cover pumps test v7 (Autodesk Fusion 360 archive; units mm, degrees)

design "cover pumps test" references "magnetventil halter cocktail", "frame", "new vertical motor mount"
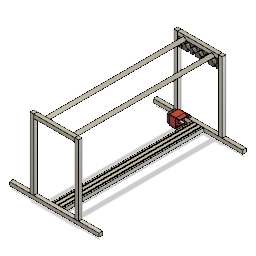
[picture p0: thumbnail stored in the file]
component_insert "Komponente einfügen1"
component_insert "Komponente einfügen2"
position "Position1"
component_insert "Komponente einfügen3"

design "new vertical motor mount"
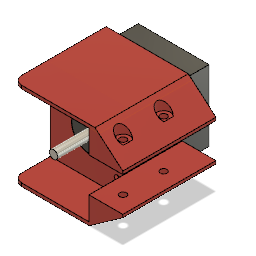
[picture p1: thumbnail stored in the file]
parameter "acryl" = 5
parameter "d6" = 13 (= "20 mm - 7 mm")
sketch "Sketch1" plane through (0, 0, 0) normal (0, 0, 1) x axis (1, 0, 0)
  line L1 (-21, 18) -> (-21, 4)
  line L2 (18, 21) -> (-18, 21)
  line L3 (21, 4) -> (21, 18)
  line L4 (-21, 21) -> (21, -21)
  line L5 (21, 21) -> (-21, -21)
  line L6 (-41, -39) -> (-41, -31)
  line L7 (41, -39) -> (-41, -39)
  line L8 (41, -31) -> (41, -39)
  line L9 (-41, -14) -> (-39, -14)
  line L10 (-41, -31) -> (-41, -17.9089)
  line L11 (41, -14) -> (39, -14)
  line L12 (41, -31) -> (41, -17.9089)
  line L13 (0, 22.5) -> (0, 1.75)
  circle C1 centre (15.5, 15.5) radius 1.7
  circle C2 centre (-15.5, 15.5) radius 1.7
  circle C3 centre (-15.5, -15.5) radius 1.7
  circle C4 centre (15.5, -15.5) radius 1.7
  circle C5 centre (-31, -29) radius 2.05
  circle C6 centre (31, -29) radius 2.05
  arc A1 centre (-39, 4) radius 18 clockwise from (-21, 4) to (-37.3636, -13.9255)
  arc A2 centre (39, 4) radius 18 clockwise from (37.3636, -13.9255) to (21, 4)
  circle C7 centre (0, 0) radius 11.5
  circle C8 centre (0, -29) radius 2.05
  arc A3 centre (-18, 18) radius 3 clockwise from (-21, 18) to (-18, 21)
  arc A4 centre (18, 18) radius 3 clockwise from (18, 21) to (21, 18)
  arc A5 centre (-37, -17.9089) radius 4 clockwise from (-41, -17.9089) to (-37.3636, -13.9255)
  arc A6 centre (37, -17.9089) radius 4 clockwise from (37.3636, -13.9255) to (41, -17.9089)
  point P6 (0, 0)
  point P1 (0, 0)
  point P7 (15.5, 15.5)
  point P27 (0, 0)
  point P28 (0, -29)
  point P4 (-21, 21)
  point P5 (21, 21)
  point P2 (21, -21)
  point P17 (-31, -29)
  parallel L1 L3
  coincident L4 P6
  coincident L5 P6
  coincident P1 P6
  coincident L5 P7
  vertical L6
  horizontal L7
  vertical L8
  horizontal L9
  vertical L10
  horizontal L11
  vertical L12
  symmetric C5 L13 C6
  tangent L9 A1
  tangent L1 A1
  tangent L11 A2
  tangent L3 A2
  equal A1 A2
  coincident P1 P27
  vertical P27 P28
  coincident P4 L1
  coincident P4 L2
  tangent L1 A3
  tangent L2 A3
  coincident P5 L2
  coincident P5 L3
  tangent L2 A4
  tangent L3 A4
  tangent L10 A5
  tangent A1 A5
  tangent L12 A6
  tangent A2 A6
  dimension "d1" distance P2 P5 = 42
  dimension "d2" distance P1 P7 = 15.5 (= "( 31 / 2 ) * 1 mm")
  dimension "d3" diameter C1 = 3.4
  dimension "d8" distance L3 L8 = 20
  dimension "d9" distance L1 L6 = 20
  dimension "d11" distance L7 L9 = 25
  dimension "d12" diameter C5 = 4.1
  dimension "d13" distance L9 P17 = 15
  dimension "d14" distance L6 P17 = 10
  dimension "d15" radius A1 = 18
  dimension "d20" diameter C7 = 23
  dimension "d23" diameter C8 = 4.1
  dimension "d30" radius A3 = 3
  dimension "d31" radius A4 = 3
  dimension "d32" radius A5 = 4
  dimension "d33" radius A6 = 4
  dimension "d5" C-Pattern1-Angle = 360
work_plane "WorkPlane1" AlongDistance 0
sketch "Path Offsets" plane through (0, 0, 1) normal (0, 0, 1) x axis (1, 0, 0)
  line L1 (-41, -39) -> (-41, -17.9089)
  line L2 (41, -39) -> (-41, -39)
  line L3 (41, -17.9089) -> (41, -39)
  line L4 (21, 18) -> (21, 4)
  line L5 (-18, 21) -> (18, 21)
  line L6 (-21, 4) -> (-21, 18)
  line L7 (-41, -39) -> (-41, -14)
  line L8 (41, -39) -> (-41, -39)
  line L9 (41, -14) -> (41, -39)
  line L10 (39, -14) -> (41, -14)
  line L11 (21, 21) -> (21, 4)
  line L12 (-21, 21) -> (21, 21)
  line L13 (-21, 4) -> (-21, 21)
  line L14 (-41, -14) -> (-39, -14)
  circle C1 centre (-15.5, -15.5) radius 1.7
  circle C2 centre (0, 0) radius 11.5
  circle C3 centre (15.5, -15.5) radius 1.7
  circle C4 centre (-31, -29) radius 2.05
  circle C5 centre (-15.5, 15.5) radius 1.7
  circle C6 centre (15.5, 15.5) radius 1.7
  circle C7 centre (31, -29) radius 2.05
  circle C8 centre (0, -29) radius 2.05
  arc A1 centre (39, 4) radius 18 clockwise from (37.3636, -13.9255) to (21, 4)
  arc A2 centre (-39, 4) radius 18 clockwise from (-21, 4) to (-37.3636, -13.9255)
  arc A3 centre (39, 4) radius 18 clockwise from (39, -14) to (21, 4)
  arc A4 centre (-39, 4) radius 18 clockwise from (-21, 4) to (-39, -14)
  arc A5 centre (18, 18) radius 3 clockwise from (18, 21) to (21, 18)
  arc A6 centre (-18, 18) radius 3 clockwise from (-21, 18) to (-18, 21)
  arc A7 centre (-37, -17.9089) radius 4 clockwise from (-41, -17.9089) to (-37.3636, -13.9255)
  arc A8 centre (37, -17.9089) radius 4 clockwise from (37.3636, -13.9255) to (41, -17.9089)
  parallel L1 L7
  parallel L2 L8
  parallel L3 L9
  concentric A1 A3
  parallel L4 L11
  parallel L5 L12
  parallel L6 L13
  concentric A2 A4
  tangent L13 A4
  tangent A4 L14
  tangent A3 L11
  tangent L10 A3
sketch "Perimeter" plane through (0, -11.5, 1) normal (0, 0, 1) x axis (1, 0, 0)
  line L1 (39, -2.5) -> (41, -2.5)
  line L2 (41, -2.5) -> (41, -27.5)
  line L3 (41, -27.5) -> (-41, -27.5)
  line L4 (-41, -27.5) -> (-41, -2.5)
  line L5 (-41, -2.5) -> (-39, -2.5)
  line L6 (-21, 15.5) -> (-21, 32.5)
  line L7 (-21, 32.5) -> (21, 32.5)
  line L8 (21, 32.5) -> (21, 15.5)
  arc A1 centre (-39, 15.5) radius 18 clockwise from (-21, 15.5) to (-39, -2.5)
  arc A2 centre (39, 15.5) radius 18 clockwise from (39, -2.5) to (21, 15.5)
sketch "Cutouts" plane through (0, -11.5, 1) normal (0, 0, 1) x axis (1, 0, 0)
  circle C1 centre (-15.5, -4) radius 1.625
  circle C2 centre (0, 11.5) radius 11.425
  circle C3 centre (15.5, -4) radius 1.625
  circle C4 centre (-31, -17.5) radius 1.975
  circle C5 centre (-15.5, 27) radius 1.625
  circle C6 centre (15.5, 27) radius 1.625
  circle C7 centre (31, -17.5) radius 1.975
  circle C8 centre (0, -17.5) radius 1.975
remove_instance "RemoveInstance1"
sketch "Sketch1" plane through (0, 0, 0) normal (0, 0, 1) x axis (1, 0, 0)
  line L1 (0, 21) -> (0, 0)
  line L2 (19, 0) -> (0, 0)
  line L3 (21, 21) -> (-21, 21)
  line L4 (21, -21) -> (21, 21)
  line L5 (-21, -21) -> (21, -21)
  line L6 (-21, 21) -> (-21, -21)
  circle C1 centre (0, 0) radius 11.5
  circle C2 centre (-15.5, 15.5) radius 1.7
  circle C3 centre (15.5, 15.5) radius 1.7
  circle C4 centre (15.5, -15.5) radius 1.7
  circle C5 centre (-15.5, -15.5) radius 1.7
  circle C6 centre (0, 0) radius 2.5
  point P1 (0, 0)
  point P2 (0, 0)
  point P4 (0, 0)
  point P5 (0, 0)
  point P15 (0, 0)
  point P11 (-21, 21)
  point P12 (21, 21)
  point P14 (-21, -21)
  coincident P1 P2
  vertical L1
  coincident P1 P4
  coincident P4 P5
  perpendicular L1 L2
  horizontal L3
  vertical L4
  horizontal L5
  vertical L6
  coincident P1 P15
  dimension "d16" diameter C1 = 23
  dimension "d18" distance P11 P12 = 42
  dimension "d19" distance P11 P14 = 42
  dimension "d21" distance L2 L3 = 21 (= "d19 / 2")
  dimension "d22" distance L1 L6 = 21 (= "d18 / 2")
  dimension "d29" diameter C6 = 5
extrude "Extrude1" new body sketch "Sketch1" profile of C1 C2 C3 C4 C5 L3 L4 L5 L6 against normal blind 47 bodies "motor"
extrude "Extrude2" add sketch "Sketch1" profile of C1 along normal blind 1.85
extrude "Extrude3" new body sketch "Sketch1" profile of C6 along normal blind 24.15 (= "71.15 mm - 47 mm") bodies "motorshaft"
combine "Combine1"
sketch "Sketch2" plane through (0, 0, 0) normal (0, 0, 1) x axis (1, 0, 0)
  line L1 (21, -21) -> (-21, -21)
  line L2 (21, 21) -> (21, -21)
  line L3 (-21, 21) -> (21, 21)
  line L4 (-21, -21) -> (-21, 21)
  line L5 (41, 10) -> (21, 10)
  line L6 (41, -10) -> (41, 10)
  line L7 (21, -10) -> (41, -10)
  line L8 (21, 10) -> (21, -10)
  line L9 (21, 0) -> (41, 0)
  line L10 (-24, 24) -> (24, 24)
  line L11 (-24, -24) -> (-24, 24)
  line L12 (24, -24) -> (-24, -24)
  line L13 (24, 24) -> (24, -24)
  line L14 (26.8952, 24) -> (24, 24)
  line L15 (41, 12) -> (26.8952, 24)
  line L16 (41, -12) -> (41, 12)
  line L17 (24, -24) -> (41, -12)
  circle C1 centre (0, 0) radius 11.5
  circle C2 centre (-15.5, 15.5) radius 1.7
  circle C3 centre (15.5, 15.5) radius 1.7
  circle C4 centre (-15.5, -15.5) radius 1.7
  circle C5 centre (15.5, -15.5) radius 1.7
  point P11 (21, 10)
  point P15 (41, 0)
  point P16 (21, 0)
  point P12 (41, 10)
  point P14 (21, -10)
  point P22 (41, 12)
  point P23 (41, -12)
  horizontal L5
  vertical L6
  horizontal L7
  vertical L8
  coincident L2 P11
  midpoint L6 P15
  midpoint L8 P16
  perpendicular L13 L14
  perpendicular L14 L16
  collinear L6 L16
  dimension "d36" distance P11 P12 = 20
  dimension "d37" distance P11 P14 = 20
  dimension "d38" distance L1 L3 = 42
  dimension "d39" distance L3 L9 = 21 (= "42.00 mm / 2")
  dimension "d40" = 3
  dimension "d41" distance P22 P23 = 24
  dimension "d42" distance L9 P22 = 12 (= "d41 / 2")
extrude "Extrude4" new body sketch "Sketch2" profile of L2 L5 L6 L7 L8 L16 against normal blind 70 and along normal blind 50 bodies "alurail"
extrude "Extrude5" new body sketch "Sketch2" profile of C1 C2 C3 C4 C5 L1 L2 L3 L4 L5 L7 L8 L12 L11 L10 L14 L15 L16 L17 along normal blind 2 bodies "holder"
copy_paste_bodies "CutPasteBodies1"
copy_paste_bodies "CutPasteBodies1"
extrude "Extrude6" add sketch "Sketch2" profile of L1 L2 L3 L4 L5 L7 L12 L11 L10 L14 L15 L16 L17 against normal blind 47
sketch "Sketch3" plane through (0, 24, 0) normal (0, 1, 0) x axis (-1, 0, 0)
  line L1 (24, 2) -> (24, -47)
  line L2 (-26.8952, 2) -> (24, 2)
  line L3 (-26.8952, -47) -> (-26.8952, 2)
  line L4 (24, -47) -> (-26.8952, -47)
sketch "Sketch1" plane through (0, -10, 0) normal (0, 1, 0) x axis (-1, 0, 0)
  line L1 (-21, 2) -> (-21, 0)
  line L2 (-41, 2) -> (-21, 2)
  line L3 (-41, -47) -> (-41, 2)
  line L4 (-21, -47) -> (-41, -47)
  line L5 (-21, 0) -> (-21, -47)
  line L6 (-31, 2) -> (-31, -47)
  line L7 (-21, -22.5) -> (-41, -22.5)
  circle C1 centre (-31, -10) radius 2
  circle C2 centre (-31, -10) radius 4
  circle C3 centre (-31, -35) radius 4
  circle C4 centre (-31, -35) radius 2
  point P7 (-31, -47)
  point P8 (-31, 2)
  point P9 (-31, -10)
  point P11 (-41, -22.5)
  point P12 (-21, -22.5)
  midpoint L4 P7
  midpoint L2 P8
  coincident L6 P9
  concentric C1 C2
  midpoint L3 P11
  coincident L5 P12
  perpendicular L5 L7
  symmetric C1 L7 C4
  symmetric C2 L7 C3
  dimension "d51" diameter C1 = 4
  dimension "d52" diameter C2 = 8
  dimension "d53" distance L2 P9 = 12
position "Position1"
extrude "Extrude7" cut sketch "Sketch1" profile of C1 C4 against normal blind 56
extrude "Extrude8" cut sketch "Sketch1" profile of C1 C2 C3 C4 against normal blind 10
position "Position2"
extrude "Extrude9" cut sketch "Sketch1" profile of C1 C2 C3 C4 along normal blind 25
sketch "Sketch2" plane through (0, 0, 2) normal (0, 0, 1) x axis (1, 0, 0)
  line L1 (21, 22) -> (41, 22)
  line L2 (21, 42) -> (21, 22)
  line L3 (41, 42) -> (21, 42)
  line L4 (41, 44) -> (41, 42)
  line L5 (26.8952, 56) -> (41, 44)
  line L6 (-24, 56) -> (26.8952, 56)
  line L7 (-24, 8) -> (-24, 56)
  line L8 (24, 8) -> (-24, 8)
  line L9 (41, 20) -> (24, 8)
  line L10 (41, 22) -> (41, 20)
  circle C1 centre (0, 32) radius 11.5
  circle C2 centre (-15.5, 47.5) radius 1.7
  circle C3 centre (15.5, 47.5) radius 1.7
  circle C4 centre (-15.5, 16.5) radius 1.7
  circle C5 centre (15.5, 16.5) radius 1.7
sketch "Sketch1" plane through (0, -32, 2) normal (0, 0, 1) x axis (1, 0, 0)
  line L1 (26.8952, 8) -> (-24, 8)
  line L2 (21, 22) -> (41, 22)
  line L3 (21, 42) -> (21, 22)
  line L4 (41, 42) -> (21, 42)
  line L5 (41, 44) -> (41, 42)
  line L6 (-24, 56) -> (26.8952, 56)
  line L7 (-24, 8) -> (-24, 56)
  line L8 (28.5, 46) -> (28.5, 42)
  line L9 (33.5, 46) -> (28.5, 46)
  line L10 (33.5, 42) -> (33.5, 46)
  line L11 (21, 42) -> (41, 42)
  line L12 (41, 22) -> (21, 22)
  line L13 (31, 42) -> (31, 22)
  line L14 (21, 32) -> (31, 32)
  line L15 (28.5, 18) -> (28.5, 22)
  line L16 (33.5, 22) -> (33.5, 18)
  line L17 (33.5, 18) -> (28.5, 18)
  line L18 (41, 42) -> (21, 42)
  line L19 (41, 46) -> (41, 42)
  line L20 (21, 46) -> (41, 46)
  line L21 (21, 42) -> (21, 46)
  line L22 (41, 46) -> (26.8952, 56)
  line L23 (21, 22) -> (21, 18)
  line L24 (21, 18) -> (41, 18)
  line L25 (41, 18) -> (41, 22)
  line L26 (41, 18) -> (26.8952, 8)
  point P10 (28.5, 42)
  point P13 (33.5, 42)
  point P18 (31, 22)
  point P19 (31, 42)
  point P20 (31, 32)
  point P21 (21, 32)
  point P22 (28.5, 22)
  point P11 (28.5, 46)
  point P23 (28.5, 18)
  point P12 (33.5, 46)
  point P24 (33.5, 18)
  point P25 (33.5, 22)
  point P3 (26.8952, 56)
  point P33 (26.8952, 8)
  point P7 (21, 42)
  point P30 (21, 22)
  point P26 (41, 42)
  point P32 (41, 22)
  point P27 (41, 46)
  point P31 (41, 18)
  point P28 (21, 46)
  point P29 (21, 18)
  coincident L4 P10
  perpendicular L4 L8
  perpendicular L8 L9
  coincident L4 P13
  perpendicular L4 L10
  midpoint L12 P18
  midpoint L4 P19
  perpendicular L4 L13
  midpoint L13 P20
  midpoint L3 P21
  perpendicular L3 L14
  symmetric P10 L14 P22
  symmetric P11 L14 P23
  symmetric P12 L14 P24
  symmetric P13 L14 P25
  horizontal L18
  vertical L19
  horizontal L20
  vertical L21
  collinear L9 L20
  symmetric P3 L14 P33
  symmetric P7 L14 P30
  symmetric L14 P26 P32
  symmetric L14 P27 P31
  symmetric L14 P28 P29
  dimension "d60" distance P11 P12 = 5 (= "acryl")
  dimension "d62" distance L6 L11 = 14
  dimension "d63" distance L11 L12 = 20
  dimension "d64" distance L3 L13 = 10
  dimension "d65" distance L8 L13 = 2.5 (= "d60 / 2")
extrude "Extrude1" new body sketch "Sketch1" profile of L1 L2 L3 L4 L6 L7 L8 L9 L10 L11 L12 L15 L16 L17 L18 L20 L21 L22 L23 L24 L26 along normal blind 5 (= "acryl")
extrude "Extrude2" cut sketch "Sketch1" profile of C1 C2 C3 C4 C5 C6 along normal blind 14
extrude "Extrude3" cut sketch "Sketch1" profile of C6 along normal blind 9
copy_paste_bodies "CopyPasteBodies1"
move "Move1"
move "Move2"
sketch "Sketch2" plane through (0, 14, 0) normal (0, -1, 0) x axis (1, 0, 0)
  line L1 (28.5, 2) -> (21, 2)
  line L2 (28.5, 7) -> (28.5, 2)
  line L3 (21, 7) -> (28.5, 7)
  line L4 (21, 2) -> (21, 7)
  line L5 (41, 15) -> (21, 15)
  line L6 (41, -62) -> (41, 15)
  line L7 (21, -62) -> (41, -62)
  line L8 (21, 15) -> (21, -62)
  line L9 (-21, 0) -> (21, 0)
  line L10 (-21, -47) -> (21, -47)
  line L11 (21, 5) -> (28.5, 5)
  line L12 (28.5, 5) -> (28.5, 0)
  line L13 (28.5, 0) -> (21, 0)
  line L14 (31, -62) -> (31, 15)
  line L15 (33.5, 5) -> (33.5, 0)
  line L16 (41, 5) -> (33.5, 5)
  line L17 (33.5, 0) -> (41, 0)
  line L18 (21, -23.5) -> (41, -23.5)
  line L19 (28.5, -47) -> (21, -47)
  line L20 (28.5, -52) -> (28.5, -47)
  line L21 (21, -52) -> (28.5, -52)
  line L22 (33.5, -47) -> (41, -47)
  line L23 (33.5, -52) -> (33.5, -47)
  line L24 (41, -52) -> (33.5, -52)
  circle C1 centre (31, -9.9855) radius 2
  circle C2 centre (31, -37.0145) radius 2
  point P18 (31, 15)
  point P19 (31, -62)
  point P14 (28.5, 5)
  point P21 (33.5, 5)
  point P15 (21, 5)
  point P22 (41, 5)
  point P16 (21, 0)
  point P23 (41, 0)
  point P17 (28.5, 0)
  point P20 (33.5, 0)
  point P24 (41, -23.5)
  point P25 (21, -23.5)
  point P28 (28.5, -52)
  point P29 (21, -52)
  point P26 (21, -47)
  point P27 (28.5, -47)
  point P31 (33.5, -47)
  point P32 (33.5, -52)
  point P33 (41, -52)
  point P30 (41, -47)
  point P34 (31, -9.9855)
  point P6 (21, 15)
  point P7 (41, 15)
  horizontal L5
  vertical L6
  horizontal L7
  vertical L8
  midpoint L5 P18
  midpoint L7 P19
  symmetric P14 L14 P21
  symmetric P15 L14 P22
  symmetric P16 L14 P23
  symmetric P17 L14 P20
  midpoint L6 P24
  midpoint L8 P25
  collinear L9 L13
  symmetric P14 L18 P28
  symmetric P15 L18 P29
  symmetric P16 L18 P26
  symmetric P17 L18 P27
  symmetric P20 L18 P31
  symmetric P21 L18 P32
  symmetric P22 L18 P33
  symmetric P23 L18 P30
  coincident L14 P34
  symmetric L18 C1 C2
  dimension "d73" distance P6 P7 = 20
  dimension "d74" distance L5 L9 = 15
  dimension "d76" distance L7 L10 = 15
  dimension "d77" distance L11 L13 = 5 (= "acryl")
  dimension "d78" diameter C1 = 4
extrude "Extrude4" new body sketch "Sketch2" profile of L2 L3 L5 L6 L7 L8 L12 L13 L15 L16 L17 L19 L20 L21 L22 L23 L24 C1 C2 no distance stored
move "Move3"
sketch "Sketch3" plane through (0, 0, 0) normal (0, 0, 1) x axis (1, 0, 0)
  line L1 (21, -21) -> (-21, -21)
  line L2 (21, 21) -> (21, -21)
  line L3 (-21, 21) -> (21, 21)
  line L4 (-21, -21) -> (-21, 21)
  line L5 (-23, 27.6906) -> (46, 27.6906)
  line L6 (-23, 0) -> (-23, 27.6906)
  line L7 (46, 14) -> (46, 27.6906)
  line L8 (41, 14) -> (46, 14)
  line L9 (41, 19) -> (41, 14)
  line L10 (-23, 0) -> (0, 0)
  line L11 (41, 19) -> (41, 14)
  line L12 (21, 19) -> (41, 19)
  line L13 (21, 0) -> (21, 19)
  line L14 (41, -14) -> (46, -14)
  line L15 (46, -14) -> (46, -27.6906)
  line L16 (-23, -27.6906) -> (46, -27.6906)
  line L17 (-23, 0) -> (-23, -27.6906)
  line L18 (21, -19) -> (41, -19)
  line L19 (21, 0) -> (21, -19)
  line L20 (41, -19) -> (41, -14)
  circle C1 centre (0, 0) radius 11.5
  circle C2 centre (-15.5, 15.5) radius 1.7
  circle C3 centre (15.5, 15.5) radius 1.7
  circle C4 centre (-15.5, -15.5) radius 1.7
  circle C5 centre (15.5, -15.5) radius 1.7
  point P15 (41, 14)
  point P16 (41, 14)
  point P2 (0, 0)
  point P19 (0, 0)
  point P13 (-23, 0)
  point P20 (41, 14)
  point P18 (41, 19)
  point P21 (41, 19)
  point P22 (21, 19)
  point P23 (21, 0)
  point P11 (46, 27.6906)
  point P26 (46, -27.6906)
  point P12 (-23, 27.6906)
  point P27 (-23, -27.6906)
  point P28 (-23, 0)
  point P14 (46, 14)
  point P24 (46, -14)
  point P25 (41, -14)
  point P32 (41, -14)
  point P29 (41, -19)
  point P30 (21, -19)
  point P31 (21, 0)
  horizontal L5
  perpendicular L5 L6
  perpendicular L5 L7
  perpendicular L7 L8
  coincident P15 P16
  coincident P2 P19
  perpendicular L4 L10
  coincident P13 L10
  coincident P16 P20
  coincident P18 P21
  coincident L2 P22
  perpendicular L2 L12
  midpoint L2 P23
  symmetric P11 L10 P26
  symmetric P12 L10 P27
  symmetric P13 L10 P28
  symmetric P14 L10 P24
  symmetric P15 L10 P25
  symmetric L10 P20 P32
  symmetric L10 P21 P29
  symmetric L10 P22 P30
  symmetric L10 P23 P31
  dimension "d81" distance L7 L9 = 5
  dimension "d82" distance L4 L6 = 2
extrude "Extrude5" new body sketch "Sketch3" profile of C1 C2 C3 C4 C5 L1 L2 L3 L4 L5 L6 L7 L8 L9 L11 L12 L13 L14 L15 L16 L17 L18 L19 L20 along normal blind 5 (= "acryl")
extrude "Extrude6" add of existing geometry blind 2
sketch "Sketch4" plane through (0, 0, 0) normal (0, 0, -1) x axis (-1, 0, 0)
  line L1 (-21, 14) -> (-28.5, 14)
  line L2 (-21, -19) -> (-21, 14)
  line L3 (-41, -19) -> (-21, -19)
  line L4 (-41, -14) -> (-41, -19)
  line L5 (-46, -14) -> (-41, -14)
  line L6 (-46, -27.6906) -> (-46, -14)
  line L7 (23, -27.6906) -> (-46, -27.6906)
  line L8 (23, 27.6906) -> (23, -27.6906)
  line L9 (-46, 27.6906) -> (23, 27.6906)
  line L10 (-46, 14) -> (-46, 27.6906)
  line L11 (-33.5, 14) -> (-46, 14)
  line L12 (-33.5, 19) -> (-33.5, 14)
  line L13 (-28.5, 19) -> (-33.5, 19)
  line L14 (-28.5, 14) -> (-28.5, 19)
  circle C1 centre (0, 0) radius 11.5
  circle C2 centre (15.5, -15.5) radius 1.7
  circle C3 centre (-15.5, 15.5) radius 1.7
  circle C4 centre (-15.5, -15.5) radius 1.7
  circle C5 centre (15.5, 15.5) radius 1.7
sketch "Sketch5" plane through (0, 19, 0) normal (0, 1, 0) x axis (-1, 0, 0)
  line L1 (-41, 0) -> (-33.5, 0)
  line L2 (-41, -47) -> (-41, 0)
  line L3 (-33.5, -47) -> (-41, -47)
  line L4 (-33.5, -52) -> (-33.5, -47)
  line L5 (-41, -52) -> (-33.5, -52)
  line L6 (-41, -62) -> (-41, -52)
  line L7 (-21, -62) -> (-41, -62)
  line L8 (-21, -52) -> (-21, -62)
  line L9 (-28.5, -52) -> (-21, -52)
  line L10 (-28.5, -47) -> (-28.5, -52)
  line L11 (-21, -47) -> (-28.5, -47)
  line L12 (-21, 0) -> (-21, -47)
  line L13 (-28.5, 0) -> (-21, 0)
  line L14 (-28.5, 5) -> (-28.5, 0)
  line L15 (-21, 5) -> (-28.5, 5)
  line L16 (-21, 15) -> (-21, 5)
  line L17 (-41, 15) -> (-21, 15)
  line L18 (-41, 5) -> (-41, 15)
  line L19 (-33.5, 5) -> (-41, 5)
  line L20 (-33.5, 0) -> (-33.5, 5)
  circle C1 centre (-31, -9.9855) radius 2
  circle C2 centre (-31, -37.0145) radius 2
  circle C3 centre (-31, -62) radius 2
  circle C4 centre (-31, 15) radius 2
  point P24 (-31, -62)
  point P25 (-31, 15)
  midpoint L7 P24
  midpoint L17 P25
  dimension "d87" diameter C3 = 4
  dimension "d88" diameter C4 = 4
extrude "Extrude7" add of existing geometry blind 6
extrude "Extrude8" add of existing geometry blind 6
extrude "Extrude9" cut sketch "Sketch5" profile of L7 L17 C3 C4 against normal blind 6
sketch "Sketch6" plane through (0, 19, 0) normal (0, 1, 0) x axis (-1, 0, 0)
  line L1 (-41, 0) -> (-33.5, 0)
  line L2 (-41, -47) -> (-41, 0)
  line L3 (-33.5, -47) -> (-41, -47)
  line L4 (-33.5, -52) -> (-33.5, -47)
  line L5 (-41, -52) -> (-33.5, -52)
  line L6 (-41, -68) -> (-41, -52)
  line L7 (-21, -68) -> (-41, -68)
  line L8 (-21, -52) -> (-21, -68)
  line L9 (-28.5, -52) -> (-21, -52)
  line L10 (-28.5, -47) -> (-28.5, -52)
  line L11 (-21, -47) -> (-28.5, -47)
  line L12 (-21, 0) -> (-21, -47)
  line L13 (-28.5, 0) -> (-21, 0)
  line L14 (-28.5, 5) -> (-28.5, 0)
  line L15 (-21, 5) -> (-28.5, 5)
  line L16 (-21, 21) -> (-21, 5)
  line L17 (-41, 21) -> (-21, 21)
  line L18 (-41, 5) -> (-41, 21)
  line L19 (-33.5, 5) -> (-41, 5)
  line L20 (-33.5, 0) -> (-33.5, 5)
  circle C1 centre (-31, 15) radius 2
  circle C2 centre (-31, -62) radius 2
  circle C3 centre (-31, -9.9855) radius 2
  circle C4 centre (-31, -37.0145) radius 2
copy_paste_bodies "CopyPasteBodies2"
move "Move4"
sketch "Sketch7" plane through (0, -14, 0) normal (0, 1, 0) x axis (-1, 0, 0)
  line L1 (-41, 0) -> (-33.5, 0)
  line L2 (-41, -47) -> (-41, 0)
  line L3 (-33.5, -47) -> (-41, -47)
  line L4 (-33.5, -52) -> (-33.5, -47)
  line L5 (-41, -52) -> (-33.5, -52)
  line L6 (-41, -68) -> (-41, -52)
  line L7 (-21, -68) -> (-41, -68)
  line L8 (-21, -52) -> (-21, -68)
  line L9 (-28.5, -52) -> (-21, -52)
  line L10 (-28.5, -47) -> (-28.5, -52)
  line L11 (-21, -47) -> (-28.5, -47)
  line L12 (-21, 0) -> (-21, -47)
  line L13 (-28.5, 0) -> (-21, 0)
  line L14 (-28.5, 5) -> (-28.5, 0)
  line L15 (-21, 5) -> (-28.5, 5)
  line L16 (-21, 21) -> (-21, 5)
  line L17 (-41, 21) -> (-21, 21)
  line L18 (-41, 5) -> (-41, 21)
  line L19 (-33.5, 5) -> (-41, 5)
  line L20 (-33.5, 0) -> (-33.5, 5)
  line L21 (-41, 5) -> (-41, 0)
  line L22 (-21, 0) -> (-21, 5)
  circle C1 centre (-31, 15) radius 2
  circle C2 centre (-31, -62) radius 2
  circle C3 centre (-31, -9.9855) radius 2
  circle C4 centre (-31, -37.0145) radius 2
  point P7 (-41, 0)
  point P26 (-41, 0)
  point P24 (-41, 5)
  point P27 (-41, 5)
  point P21 (-21, 5)
  point P28 (-21, 5)
  point P18 (-21, 0)
  point P29 (-21, 0)
  coincident P7 P26
  coincident P24 P27
  coincident P21 P28
  coincident P18 P29
extrude "Extrude10" add sketch "Sketch7" profile of L1 L13 L14 L15 L19 L20 L21 L22 no distance stored
extrude "Extrude10" cut of existing geometry blind -16 (= "-49 mm + 33 mm")
sketch "Sketch4" plane through (0, -42, 0) normal (0, 1, 0) x axis (-1, 0, 0)
  line L1 (-21, 2) -> (-41, 2)
  circle C1 centre (-31, -10) radius 4
  circle C2 centre (-31, -10) radius 2
  circle C3 centre (-31, 14) radius 4
  circle C4 centre (-31, 14) radius 2
  concentric C1 C2
  horizontal L1
  symmetric C1 L1 C3
  symmetric C2 L1 C4
  dimension "d99" diameter C2 = 4
  dimension "d100" diameter C1 = 8
sketch "Sketch5" plane through (0, 0, 2) normal (0, 0, 1) x axis (1, 0, 0)
  line L1 (21, -10) -> (41, -10)
  line L2 (21, 10) -> (21, -10)
  line L3 (41, 10) -> (21, 10)
  line L4 (41, 12) -> (41, 10)
  line L5 (26.8952, 24) -> (41, 12)
  line L6 (-24, 24) -> (26.8952, 24)
  line L7 (-24, -24) -> (-24, 24)
  line L8 (24, -24) -> (-24, -24)
  line L9 (41, -12) -> (24, -24)
  line L10 (41, -10) -> (41, -12)
  line L11 (21, 24) -> (21, 10)
  line L12 (21, -24) -> (21, -10)
  line L13 (18.3503, -24) -> (18.3503, 24)
  circle C1 centre (0, 0) radius 11.5
  circle C2 centre (-15.5, 15.5) radius 1.7
  circle C3 centre (15.5, 15.5) radius 1.7
  circle C4 centre (-15.5, -15.5) radius 1.7
  circle C5 centre (15.5, -15.5) radius 1.7
  point P9 (21, 10)
  point P17 (21, 10)
  point P18 (21, 24)
  point P8 (21, -10)
  point P19 (21, -10)
  point P20 (21, -24)
  point P21 (18.3503, 24)
  point P22 (18.3503, -24)
  coincident P9 P17
  coincident L6 P18
  perpendicular L6 L11
  coincident P8 P19
  coincident L8 P20
  perpendicular L8 L12
  coincident L6 P21
  coincident L8 P22
  perpendicular L8 L13
extrude "Extrude11" add sketch "Sketch5" profile of L1 L3 L4 L5 L6 L8 L9 L10 L11 L12 along normal blind 22
extrude "Extrude12" cut sketch "Sketch4" profile of C4 along normal blind 85
extrude "Extrude13" cut sketch "Sketch4" profile of C3 C4 along normal blind 25
sketch "Sketch1" plane through (0, -42, 0) normal (0, 1, 0) x axis (-1, 0, 0)
sketch "Sketch2" plane through (0, -42, 0) normal (0, 1, 0) x axis (-1, 0, 0)
  circle C1 centre (-31, -10) radius 2
  circle C2 centre (-31, -10) radius 4
  circle C3 centre (-31, 14) radius 4
  circle C4 centre (-31, 14) radius 2
  concentric C1 C2
  dimension "d107" diameter C1 = 4
  dimension "d108" diameter C2 = 8
position "Position3"
extrude "Extrude14" cut sketch "Sketch2" profile of C3 C4 against normal blind 15
sketch "Sketch3" plane through (0, -51, 0) normal (0, 1, 0) x axis (-1, 0, 0)
  line L1 (24, -31) -> (-26.8952, -31)
  line L2 (24, 2) -> (24, -31)
  line L3 (-21, 2) -> (24, 2)
  line L4 (-21, 24) -> (-21, 2)
  line L5 (-26.8952, 24) -> (-21, 24)
  line L6 (-26.8952, -31) -> (-26.8952, 24)
sketch "Sketch4" plane through (0, 0, -31) normal (0, 0, -1) x axis (-1, 0, 0)
  line L1 (-41, -85) -> (-21, -85)
  line L2 (-41, -87) -> (-41, -85)
  line L3 (-24, -99) -> (-41, -87)
  line L4 (24, -99) -> (-24, -99)
  line L5 (24, -51) -> (24, -99)
  line L6 (-26.8952, -51) -> (24, -51)
  line L7 (-41, -63) -> (-26.8952, -51)
  line L8 (-41, -65) -> (-41, -63)
  line L9 (-21, -65) -> (-41, -65)
  line L10 (-21, -54) -> (-21, -65)
  line L11 (21, -54) -> (-21, -54)
  line L12 (21, -96) -> (21, -54)
  line L13 (-21, -96) -> (21, -96)
  line L14 (-21, -85) -> (-21, -96)
  line L15 (-24.5443, -49) -> (-26.8952, -51)
  line L16 (24, -49) -> (-24.5443, -49)
  line L17 (24, -51) -> (24, -49)
  line L18 (-40, -75) -> (24, -75)
  line L19 (-21.1667, -101) -> (-24, -99)
  line L20 (24, -101) -> (-21.1667, -101)
  line L21 (24, -99) -> (24, -101)
  point P8 (-26.8952, -51)
  point P16 (-26.8952, -51)
  point P7 (24, -51)
  point P19 (24, -51)
  point P20 (24, -75)
  point P5 (-24, -99)
  point P22 (-24, -99)
  point P6 (24, -99)
  point P25 (24, -99)
  coincident P8 P16
  parallel L7 L15
  parallel L6 L16
  coincident P7 P19
  perpendicular L16 L17
  midpoint L5 P20
  perpendicular L5 L18
  coincident P5 P22
  parallel L3 L19
  parallel L4 L20
  coincident P6 P25
  perpendicular L20 L21
  dimension "d111" distance L6 L16 = 2
  dimension "d112" distance L4 L20 = 2 (= "d111")
extrude "Extrude15" add sketch "Sketch4" profile of L4 L6 L15 L16 L17 L19 L20 L21 against normal blind 55
fillet "Fillet1" radius 5
extrude "Extrude16" add of existing geometry blind 0.15
extrude "Extrude17" cut of existing geometry blind -0.2
extrude "Extrude18" cut of existing geometry blind -0.2
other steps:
base_feature "Base Feature1" bodies "motor", "motorshaft"
base_feature "Base Feature1" bodies "alurail"
base_feature "Base Feature1"
base_feature "Base Feature2"
create_component "CreateComponent3"
create_component "CreateComponent1"
create_component "CreateComponent2"
remove_body "RemoveBody1"
remove_body "RemoveBody2"
create_component "CreateComponent3"
remove_body "RemoveBody3"
create_component "CreateComponent4"
create_component "CreateComponent5"
create_component "CreateComponent6"
named bodies: "motor", "motorshaft", "alurail", "holder"

design "magnetventil halter cocktail"
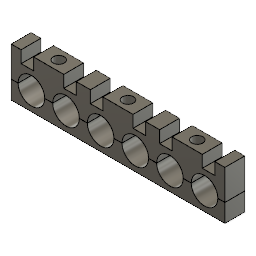
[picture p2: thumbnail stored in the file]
parameter "schrauben" = 4.2
parameter "schrauben_1" = 4.2
sketch "Sketch1" plane through (0, 0, 0) normal (0, 0, 1) x axis (1, 0, 0)
  line L1 (215, 0) -> (0, 0)
  line L2 (215, 36.5) -> (215, 0)
  line L3 (0, 36.5) -> (215, 36.5)
  line L4 (0, 0) -> (0, 36.5)
  line L5 (124.75, 18.25) -> (90.25, 18.25)
  line L6 (107.5, 18.25) -> (124.75, 18.25)
  line L7 (107.5, 0) -> (107.5, 18.25)
  line L8 (215, 0) -> (0, 0)
  line L9 (215, 36.5) -> (215, 0)
  line L10 (0, 0) -> (0, 36.5)
  line L11 (0, 18.25) -> (215, 18.25)
  line L12 (21.25, 36.5) -> (21.25, 18.25)
  line L13 (55.75, 36.5) -> (55.75, 18.25)
  line L14 (159.25, 36.5) -> (159.25, 18.25)
  line L15 (193.75, 36.5) -> (193.75, 18.25)
  circle C1 centre (21.25, 18.25) radius 13.25
  circle C2 centre (55.75, 18.25) radius 13.25
  circle C3 centre (90.25, 18.25) radius 13.25
  circle C4 centre (124.75, 18.25) radius 13.25
  circle C5 centre (159.25, 18.25) radius 13.25
  circle C6 centre (193.75, 18.25) radius 13.25
  point P1 (0, 0)
  point P2 (0, 0)
  point P8 (90.25, 18.25)
  point P12 (90.25, 18.25)
  point P9 (124.75, 18.25)
  point P13 (124.75, 18.25)
  point P14 (107.5, 18.25)
  point P15 (107.5, 0)
  point P17 (215, 36.5)
  point P19 (215, 18.25)
  point P20 (0, 18.25)
  point P6 (21.25, 18.25)
  point P21 (21.25, 18.25)
  point P22 (21.25, 36.5)
  point P7 (55.75, 18.25)
  point P23 (55.75, 18.25)
  point P24 (55.75, 36.5)
  point P10 (159.25, 18.25)
  point P25 (159.25, 18.25)
  point P26 (159.25, 36.5)
  point P11 (193.75, 18.25)
  point P27 (193.75, 18.25)
  point P28 (193.75, 36.5)
  point P3 (215, 0)
  point P5 (0, 36.5)
  horizontal L1
  vertical L2
  horizontal L3
  vertical L4
  coincident P1 P2
  coincident P8 P12
  coincident P9 P13
  midpoint L5 P14
  coincident L1 P15
  perpendicular L1 L7
  midpoint L1 P15
  horizontal L8
  vertical L9
  vertical L10
  coincident L2 P17
  midpoint L9 P19
  midpoint L10 P20
  coincident P6 P21
  coincident L3 P22
  perpendicular L3 L12
  coincident P7 P23
  coincident L3 P24
  perpendicular L11 L13
  coincident P10 P25
  coincident L3 P26
  perpendicular L3 L14
  coincident P11 P27
  coincident L3 P28
  perpendicular L3 L15
  dimension "d2" distance P2 P3 = 215
  dimension "d3" distance P2 P5 = 36.5 (= "d9 * 2")
  dimension "d4" diameter C1 = 26.5 (= "Diameter Dimension-2")
  dimension "d9" distance L1 P14 = 18.25 (= "Linear Dimension-4")
  dimension "d7" value = 34.5 (= "R-Pattern1-uDistance")
  dimension "d8" R-Pattern1-vDistance = 0
extrude "Extrude1" new body sketch "Sketch1" profile of L2 L3 L4 C1 C2 C3 C4 C5 C6 L6 L9 L10 L11 along normal blind 10
extrude "Extrude2" new body sketch "Sketch1" profile of L1 L2 L4 C1 C2 C3 C4 C5 C6 L6 L8 L9 L10 L11 along normal blind 10
sketch "Sketch3" plane through (0, 0, 0) normal (0, 0, 1) x axis (1, 0, 0)
sketch "Sketch4" plane through (0, 36.5, 0) normal (0, 1, 0) x axis (-1, 0, 0)
  line L1 (0, 0) -> (-215, 0)
  line L2 (0, 10) -> (0, 0)
  line L3 (-215, 10) -> (0, 10)
  line L4 (-215, 0) -> (-215, 10)
  line L5 (-8, 10) -> (-34.5, 10)
  line L6 (-21.25, 10) -> (-21.25, 0)
  line L7 (-42.5, 10) -> (-69, 10)
  line L8 (-55.75, 10) -> (-55.75, 0)
  line L9 (-21.25, 5) -> (-55.75, 5)
  line L10 (-107.5, 10) -> (-107.5, 0)
  line L11 (-146, 10) -> (-172.5, 10)
  line L12 (-159.25, 10) -> (-159.25, 0)
  line L13 (-180.5, 10) -> (-207, 10)
  line L14 (-193.75, 10) -> (-193.75, 0)
  line L15 (-193.75, 5) -> (-159.25, 5)
  circle C1 centre (-38.5, 5) radius 2.1
  circle C2 centre (-107.5, 5) radius 2.1
  circle C3 centre (-176.5, 5) radius 2.1
  circle C4 centre (-38.5, 5) radius 3.65
  circle C5 centre (-107.5, 5) radius 3.65
  circle C6 centre (-176.5, 5) radius 3.65
  point P6 (-21.25, 0)
  point P9 (-21.25, 0)
  point P10 (-21.25, 10)
  point P11 (-55.75, 0)
  point P14 (-55.75, 0)
  point P15 (-55.75, 10)
  point P16 (-55.75, 5)
  point P17 (-21.25, 5)
  point P18 (-38.5, 5)
  point P19 (-107.5, 0)
  point P20 (-107.5, 10)
  point P21 (-107.5, 5)
  point P22 (-159.25, 0)
  point P25 (-159.25, 0)
  point P26 (-159.25, 10)
  point P27 (-193.75, 0)
  point P30 (-193.75, 0)
  point P31 (-193.75, 10)
  point P32 (-159.25, 5)
  point P33 (-193.75, 5)
  point P34 (-176.5, 5)
  coincident P6 P9
  midpoint L5 P10
  coincident P11 P14
  midpoint L7 P15
  midpoint L8 P16
  midpoint L6 P17
  midpoint L9 P18
  midpoint L1 P19
  midpoint L3 P20
  midpoint L10 P21
  coincident P22 P25
  midpoint L11 P26
  coincident P27 P30
  midpoint L13 P31
  midpoint L12 P32
  midpoint L14 P33
  midpoint L15 P34
  concentric C1 C4
  concentric C2 C5
  concentric C3 C6
  dimension "d17" diameter C1 = 4.2 (= "schrauben_1")
  dimension "d18" diameter C2 = 4.2 (= "schrauben_1")
  dimension "d19" diameter C3 = 4.2 (= "schrauben_1")
  dimension "d20" diameter C4 = 7.3
  dimension "d21" diameter C5 = 7.3
  dimension "d22" diameter C6 = 7.3
extrude "Extrude3" cut sketch "Sketch4" profile of C1 C2 C3 against normal blind 45
extrude "Extrude4" cut sketch "Sketch4" profile of C1 C2 C3 C4 C5 C6 against normal blind 5
extrude "Extrude5" add of existing geometry blind 5
extrude "Extrude6" add of existing geometry blind 5
extrude "Extrude7" add of existing geometry blind 5
extrude "Extrude8" add of existing geometry blind 5
sketch "Sketch1" plane through (0, 36.5, 0) normal (0, 1, 0) x axis (-1, 0, 0)
  line L1 (0, 15) -> (0, -5)
  line L2 (-215, 15) -> (0, 15)
  line L3 (-215, -5) -> (-215, 15)
  line L4 (0, -5) -> (-215, -5)
  line L5 (-66, -5) -> (-53.5, -5)
  line L6 (-66, 15) -> (-66, -5)
  line L7 (-53.5, 15) -> (-66, 15)
  line L8 (-53.5, -5) -> (-53.5, 15)
  line L9 (-92.5, -5) -> (-80, -5)
  line L10 (-92.5, 15) -> (-92.5, -5)
  line L11 (-80, 15) -> (-92.5, 15)
  line L12 (-80, -5) -> (-80, 15)
  line L13 (-135, -5) -> (-122.5, -5)
  line L14 (-135, 15) -> (-135, -5)
  line L15 (-122.5, 15) -> (-135, 15)
  line L16 (-122.5, -5) -> (-122.5, 15)
  line L17 (-161.5, 15) -> (-149, 15)
  line L18 (-161.5, -5) -> (-161.5, 15)
  line L19 (-149, -5) -> (-161.5, -5)
  line L20 (-149, 15) -> (-149, -5)
  line L21 (-204, -5) -> (-191.5, -5)
  line L22 (-204, 15) -> (-204, -5)
  line L23 (-191.5, 15) -> (-204, 15)
  line L24 (-191.5, -5) -> (-191.5, 15)
  line L25 (-23.5, -5) -> (-11, -5)
  line L26 (-23.5, 15) -> (-23.5, -5)
  line L27 (-11, 15) -> (-23.5, 15)
  line L28 (-11, -5) -> (-11, 15)
  circle C1 centre (-107.5, 5) radius 3.65
  circle C2 centre (-176.5, 5) radius 3.65
  circle C3 centre (-38.5, 5) radius 3.65
  point P9 (-53.5, -5)
  point P18 (-122.5, -5)
  point P22 (-149, 15)
  point P26 (-191.5, -5)
  point P30 (-11, -5)
  point P10 (-66, -5)
  point P13 (-80, -5)
  point P14 (-92.5, -5)
  point P19 (-135, -5)
  point P23 (-161.5, 15)
  point P27 (-204, -5)
  point P31 (-23.5, -5)
  point P4 (-38.5, 5)
  point P3 (-176.5, 5)
  point P2 (-107.5, 5)
  horizontal L5
  vertical L6
  horizontal L7
  vertical L8
  coincident L4 P9
  horizontal L9
  vertical L10
  horizontal L11
  vertical L12
  horizontal L13
  vertical L14
  horizontal L15
  vertical L16
  coincident L4 P18
  horizontal L17
  vertical L18
  horizontal L19
  vertical L20
  coincident L2 P22
  horizontal L21
  vertical L22
  horizontal L23
  vertical L24
  coincident L4 P26
  horizontal L25
  vertical L26
  horizontal L27
  vertical L28
  coincident L4 P30
  collinear L4 L9
  collinear L2 L11
  dimension "d1" distance P9 P10 = 12.5
  dimension "d15" distance P13 P14 = 12.5
  dimension "d16" distance P18 P19 = 12.5
  dimension "d35" distance P22 P23 = 12.5
  dimension "d36" distance P26 P27 = 12.5
  dimension "d37" distance P30 P31 = 12.5
  dimension "d38" distance P4 L8 = 15
  dimension "d39" distance P3 L18 = 15
  dimension "d40" distance P2 L10 = 15
  dimension "d41" distance P2 L16 = 15
  dimension "d42" distance P3 L24 = 15
  dimension "d43" distance P4 L26 = 15
extrude "Extrude1" new body sketch "Sketch1" against normal blind 2
extrude "Extrude2" add sketch "Sketch1" profile of C1 C2 C3 L1 L2 L3 L4 L6 L8 L10 L12 L14 L16 L18 L20 L22 L24 L26 L28 along normal blind 12
extrude "Extrude3" add of existing geometry blind 1
sketch "Sketch2" plane through (0, 48.5, 0) normal (0, 1, 0) x axis (-1, 0, 0)
  line L1 (-23.5, 15) -> (-23.5, -5)
  line L2 (-53.5, 15) -> (-23.5, 15)
  line L3 (-53.5, -5) -> (-53.5, 15)
  line L4 (-23.5, -5) -> (-53.5, -5)
  circle C1 centre (-38.5, 5) radius 3.65
  circle C2 centre (-38.5, 5) radius 5.5
  concentric C1 C2
  dimension "d50" diameter C2 = 11
extrude "Extrude4" cut sketch "Sketch2" profile of C1 C2 against normal blind 12
sketch "Sketch3" plane through (0, 48.5, 0) normal (0, 1, 0) x axis (-1, 0, 0)
  line L1 (-122.5, -5) -> (-122.5, 15)
  line L2 (-92.5, -5) -> (-122.5, -5)
  line L3 (-92.5, 15) -> (-92.5, -5)
  line L4 (-122.5, 15) -> (-92.5, 15)
  circle C1 centre (-107.5, 5) radius 3.65
  circle C2 centre (-107.5, 5) radius 5.5
  concentric C1 C2
  dimension "d53" diameter C2 = 11
sketch "Sketch4" plane through (0, 48.5, 0) normal (0, 1, 0) x axis (-1, 0, 0)
  line L1 (-191.5, 15) -> (-161.5, 15)
  line L2 (-191.5, -5) -> (-191.5, 15)
  line L3 (-161.5, -5) -> (-191.5, -5)
  line L4 (-161.5, 15) -> (-161.5, -5)
  circle C1 centre (-176.5, 5) radius 3.65
sketch "Sketch5" plane through (0, 0, 0) normal (0, 1, 0) x axis (1, 0, 0)
sketch "Sketch6" plane through (0, 48.5, 0) normal (0, 1, 0) x axis (-1, 0, 0)
  circle C1 centre (-176.5, 5) radius 5.5
  point P2 (-176.5, 5)
  point P3 (-176.5, 5)
  coincident P2 P3
  dimension "d54" diameter C1 = 11
extrude "Extrude5" cut sketch "Sketch6" against normal blind 12
extrude "Extrude6" cut sketch "Sketch3" profile of C1 C2 against normal blind 12
extrude "Extrusion7" cut of existing geometry blind -1
extrude "Extrusion10" cut of existing geometry blind -1
extrude "Extrusion8" cut of existing geometry blind -1
extrude "Extrusion12" cut of existing geometry blind -1
combine "Combine1"
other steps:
extrude "Extrusion9" cut of existing geometry blind -1
extrude "Extrusion11" cut of existing geometry blind -1
create_component "CreateComponent2"
remove_body "RemoveBody1"

design "frame"
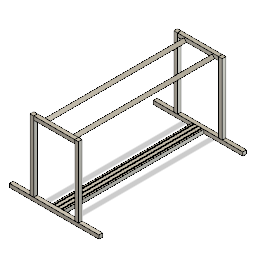
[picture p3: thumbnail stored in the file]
parameter "alurail" = 20
sketch "Sketch2" plane through (0, 0, 0) normal (0, 0, 1) x axis (1, 0, 0)
  line L1 (-255, 0) -> (0, 0)
  line L2 (-255, 20) -> (-255, 0)
  line L3 (0, 20) -> (-255, 20)
  line L4 (0, 0) -> (0, 20)
  line L5 (0, 10) -> (-255, 10)
  line L6 (-235, 20) -> (-255, 20)
  line L7 (-235, 390) -> (-235, 20)
  line L8 (-255, 390) -> (-235, 390)
  line L9 (-255, 20) -> (-255, 390)
  line L10 (-20, 20) -> (0, 20)
  line L11 (-20, 390) -> (-20, 20)
  line L12 (0, 390) -> (-20, 390)
  line L13 (0, 20) -> (0, 390)
  line L14 (-20, 390) -> (-235, 390)
  line L15 (-20, 370) -> (-20, 390)
  line L16 (-235, 370) -> (-20, 370)
  line L17 (-235, 390) -> (-235, 370)
  line L18 (-10, 20) -> (-10, 390)
  line L19 (-245, 20) -> (-245, 390)
  line L20 (-20, 380) -> (-235, 380)
  point P1 (0, 0)
  point P2 (0, 0)
  point P6 (-255, 10)
  point P7 (0, 10)
  point P14 (-235, 390)
  point P18 (-10, 390)
  point P19 (-10, 20)
  point P20 (-245, 390)
  point P21 (-245, 20)
  point P22 (-235, 380)
  point P23 (-20, 380)
  point P5 (0, 20)
  point P4 (-255, 20)
  point P8 (-235, 20)
  point P17 (-235, 370)
  horizontal L1
  vertical L2
  horizontal L3
  vertical L4
  coincident P1 P2
  midpoint L2 P6
  midpoint L4 P7
  horizontal L6
  vertical L7
  horizontal L8
  vertical L9
  horizontal L10
  vertical L11
  horizontal L12
  vertical L13
  collinear L8 L12
  horizontal L14
  vertical L15
  horizontal L16
  vertical L17
  coincident L7 P14
  collinear L8 L14
  midpoint L12 P18
  midpoint L10 P19
  midpoint L8 P20
  midpoint L6 P21
  midpoint L17 P22
  midpoint L15 P23
  dimension "d5" distance P2 P5 = 20 (= "alurail")
  dimension "d6" distance P4 P8 = 20 (= "alurail")
  dimension "d9" distance L11 L13 = 20 (= "alurail")
  dimension "d10" distance P14 P17 = 20 (= "alurail")
  dimension "d11" distance L1 L14 = 390
  dimension "d50" distance L7 L11 = 215
extrude "Extrude1" new body sketch "Sketch2" profile of L3 L6 L7 L8 L9 L10 L11 L12 L13 L15 L17 no distance stored
extrude "Extrude2" new body sketch "Sketch2" profile of L1 L2 L3 L4 L6 L7 L10 L11 L14 L15 L16 L17 no distance stored
sketch "Sketch3" plane through (0, 0, 0) normal (0, 0, 1) x axis (1, 0, 0)
sketch "Sketch4" plane through (0, 0, 0) normal (1, 0, 0) x axis (0, 0, -1)
  line L1 (0, 20) -> (0, 390)
  line L2 (20, 20) -> (0, 20)
  line L3 (20, 390) -> (20, 20)
  line L4 (0, 390) -> (20, 390)
  line L5 (755, 20) -> (20, 20)
  line L6 (755, 0) -> (755, 20)
  line L7 (20, 0) -> (755, 0)
  line L8 (20, 20) -> (20, 0)
  line L9 (20, 10) -> (755, 10)
  point P4 (20, 20)
  point P6 (20, 20)
  point P10 (755, 10)
  point P11 (20, 10)
  point P7 (755, 20)
  point P9 (20, 0)
  horizontal L5
  vertical L6
  horizontal L7
  vertical L8
  coincident P4 P6
  midpoint L6 P10
  midpoint L8 P11
  dimension "d16" distance P6 P7 = 735 (= "775 mm - ( alurail * 2 )")
  dimension "d17" distance P6 P9 = 20 (= "alurail")
extrude "Extrude3" new body sketch "Sketch4" profile of L5 L6 L7 L8 no distance stored
copy_paste_bodies "CopyPasteBodies1"
move "Move1"
move "Move2"
sketch "Sketch5" plane through (0, 0, -20) normal (0, 0, 1) x axis (1, 0, 0)
  line L1 (0, 390) -> (0, 370)
  line L2 (-20, 390) -> (0, 390)
  line L3 (-20, 370) -> (-20, 390)
  line L4 (0, 370) -> (-20, 370)
  line L5 (0, 370) -> (-20, 390)
  line L6 (0, 390) -> (-20, 370)
  circle C1 centre (-10, 380) radius 2
  point P4 (-20, 390)
  point P6 (-20, 390)
  point P2 (0, 370)
  point P7 (0, 370)
  point P5 (-20, 370)
  point P8 (-20, 370)
  point P3 (0, 390)
  point P9 (0, 390)
  point P10 (-10, 380)
  coincident P4 P6
  coincident P2 P7
  coincident P5 P8
  coincident P3 P9
  midpoint L5 P10
  dimension "d20" diameter C1 = 4
move "Move3"
move "Move4"
move "Move5"
extrude "Extrude4" add of existing geometry blind 107.5 (= "( ( 440 - 225 ) / 2 ) * 1 mm")
extrude "Extrude5" add of existing geometry blind 107.5 (= "( ( 440 - 225 ) / 2 ) * 1 mm")
sketch "Sketch6" plane through (0, 20, 0) normal (0, 1, 0) x axis (-1, 0, 0)
  line L1 (-107.5, 0) -> (362.5, 0)
  line L2 (-107.5, -20) -> (-107.5, 0)
  line L3 (362.5, -20) -> (-107.5, -20)
  line L4 (362.5, 0) -> (362.5, -20)
  line L5 (112.5, -20) -> (172.5, -20)
  line L6 (112.5, -755) -> (112.5, -20)
  line L7 (172.5, -755) -> (112.5, -755)
  line L8 (172.5, -20) -> (172.5, -755)
  line L9 (142.5, -20) -> (142.5, -755)
  line L10 (145, -755) -> (160, -755)
  line L11 (145, -20) -> (145, -755)
  line L12 (160, -20) -> (145, -20)
  line L13 (160, -755) -> (160, -20)
  line L14 (140, -755) -> (145, -755)
  line L15 (140, -20) -> (140, -755)
  line L16 (145, -20) -> (140, -20)
  line L17 (145, -755) -> (145, -20)
  line L18 (165, -755) -> (160, -755)
  line L19 (165, -20) -> (165, -755)
  line L20 (160, -20) -> (165, -20)
  line L21 (160, -755) -> (160, -20)
  line L22 (140, -20) -> (140, -755)
  line L23 (125, -20) -> (140, -20)
  line L24 (140, -755) -> (125, -755)
  line L25 (125, -755) -> (125, -20)
  line L26 (120, -755) -> (125, -755)
  line L27 (125, -20) -> (120, -20)
  line L28 (125, -755) -> (125, -20)
  line L29 (120, -20) -> (120, -755)
  line L30 (-4.1421, -755) -> (10, -755)
  point P6 (172.5, -20)
  point P10 (142.5, -755)
  point P11 (142.5, -20)
  point P12 (160, -755)
  point P18 (140, -20)
  point P16 (145, -755)
  point P21 (165, -20)
  point P26 (125, -755)
  point P13 (145, -755)
  point P23 (140, -755)
  point P14 (145, -20)
  point P24 (140, -20)
  point P15 (160, -20)
  point P25 (125, -20)
  point P20 (165, -755)
  point P27 (120, -755)
  point P28 (120, -20)
  point P22 (160, -20)
  point P29 (125, -20)
  horizontal L5
  vertical L6
  horizontal L7
  vertical L8
  coincident L3 P6
  midpoint L7 P10
  midpoint L5 P11
  horizontal L10
  vertical L11
  horizontal L12
  vertical L13
  coincident L7 P12
  horizontal L14
  vertical L15
  horizontal L16
  vertical L17
  coincident L5 P18
  coincident L7 P16
  collinear L11 L17
  horizontal L18
  vertical L19
  horizontal L20
  vertical L21
  coincident L5 P21
  symmetric L9 P12 P26
  symmetric L9 P13 P23
  symmetric L9 P14 P24
  symmetric L9 P15 P25
  symmetric L9 P20 P27
  symmetric L9 P21 P28
  symmetric L9 P22 P29
  collinear L7 L30
  dimension "d25" distance L6 L8 = 60
  dimension "d26" = 440
  dimension "d27" distance L4 L9 = 220 (= "440.00 mm / 2")
  dimension "d28" distance P12 P13 = 15
  dimension "d29" distance L15 L17 = 5
  dimension "d30" distance L9 L15 = 2.5 (= "d29 / 2")
  dimension "d31" distance L13 L19 = 5 (= "d29")
extrude "Extrude6" new body sketch "Sketch6" profile of L3 L5 L6 L7 L8 L10 L11 L12 L13 L15 L17 L19 L21 L22 L23 L24 L25 L28 L29 distance 20 (= "alurail") bodies "rail"
extrude "Extrude7" add sketch "Sketch6" profile of L3 L5 L7 L11 L13 L14 L15 L16 L17 L18 L19 L20 L21 L22 L25 L26 L27 L28 L29 distance 10
move "Move6"
sketch "Sketch7" plane through (0, 20, 0) normal (0, 1, 0) x axis (-1, 0, 0)
  line L1 (172.5, -40) -> (112.5, -40)
  line L2 (172.5, 0) -> (172.5, -40)
  line L3 (112.5, 0) -> (172.5, 0)
  line L4 (112.5, -40) -> (112.5, 0)
  line L5 (112.5, -20) -> (172.5, -20)
  line L6 (-107.5, 0) -> (362.5, 0)
  line L7 (127.5, 0) -> (142.5, -40)
  line L8 (172.5, -9.4025) -> (112.5, -9.4025)
  circle C1 centre (136.977, -25.2721) radius 2.1
  circle C2 centre (142.5, -9.4025) radius 2.1
  circle C3 centre (156.977, -25.2721) radius 2.1
  circle C4 centre (116.977, -25.2721) radius 2.1
  circle C5 centre (122.5, -9.4025) radius 2.1
  circle C6 centre (162.5, -9.4025) radius 2.1
  point P6 (172.5, -20)
  point P7 (112.5, -20)
  point P12 (142.5, -40)
  point P13 (127.5, 0)
  point P14 (112.5, -9.4025)
  point P15 (172.5, -9.4025)
  point P16 (136.977, -25.2721)
  point P17 (142.5, -9.4025)
  horizontal L1
  vertical L2
  horizontal L3
  vertical L4
  coincident L2 P6
  coincident L4 P7
  collinear L3 L6
  midpoint L1 P12
  midpoint L6 P13
  coincident L4 P14
  coincident L2 P15
  perpendicular L2 L8
  coincident L7 P16
  midpoint L8 P17
  dimension "d36" distance L1 L5 = 20
  dimension "d37" diameter C1 = 4.2 (= "d38")
  dimension "d38" diameter C2 = 4.2
  dimension "d41" R-Pattern1-uDistance = -20
  dimension "d42" R-Pattern1-vDistance = 0
  dimension "d45" R-Pattern2-uDistance = 20
  dimension "d46" R-Pattern2-vDistance = 0
extrude "Extrude8" new body sketch "Sketch7" profile of L1 L2 L3 L4 L5 L6 C1 C2 C3 C4 C5 C6 along normal blind 5
sketch "Sketch8" plane through (0, 25, 0) normal (0, 1, 0) x axis (-1, 0, 0)
  line L1 (172.5, 0) -> (172.5, -40)
  line L2 (112.5, 0) -> (172.5, 0)
  line L3 (112.5, -40) -> (112.5, 0)
  line L4 (172.5, -40) -> (112.5, -40)
  circle C1 centre (142.5, -9.4025) radius 2.1
  circle C2 centre (122.5, -9.4025) radius 2.1
  circle C3 centre (136.977, -25.2721) radius 2.1
  circle C4 centre (162.5, -9.4025) radius 2.1
  circle C5 centre (156.977, -25.2721) radius 2.1
  circle C6 centre (116.977, -25.2721) radius 2.1
copy_paste_bodies "Körper ausschneiden/einfügen"
move "Verschieben7"
move "Verschieben8"
move "Verschieben9"
copy_paste "Kopieren/Einfügen"
sketch "Skizze" plane through (0, 20, 0) normal (0, 1, 0) x axis (-1, 0, 0)
  line L1 (-107.5, 0) -> (362.5, 0)
  line L2 (-107.5, -20) -> (-107.5, 0)
  line L3 (362.5, -20) -> (-107.5, -20)
  line L4 (362.5, 0) -> (362.5, -20)
  line L5 (127.5, -20) -> (127.5, 0)
  line L6 (130, 0) -> (130, -20)
  point P6 (127.5, 0)
  point P7 (127.5, -20)
  point P8 (130, -20)
  point P9 (130, 0)
  midpoint L1 P6
  midpoint L3 P7
  coincident L3 P8
  coincident L1 P9
  perpendicular L1 L6
  dimension "d49" distance L5 L6 = 2.5
move "Verschieben10"
move "Verschieben11"
move "Verschieben12"
move "Verschieben13"
move "Verschieben14"
move "Move15"
move "Move16"
move "Move17"
move "Move18"
sketch "Sketch10" plane through (0, 0, -755) normal (0, 0, 1) x axis (1, 0, 0)
  line L1 (-20, 370) -> (-235, 370)
  line L2 (-20, 390) -> (-20, 370)
  line L3 (-235, 390) -> (-20, 390)
  line L4 (-235, 370) -> (-235, 390)
  line L5 (-127.5, 370) -> (-127.5, 390)
  line L6 (-187.5, 370) -> (-187.5, 390)
  line L7 (-67.5, 370) -> (-67.5, 390)
  point P6 (-127.5, 390)
  point P7 (-127.5, 370)
  point P8 (-187.5, 390)
  point P9 (-187.5, 370)
  point P10 (-67.5, 390)
  point P11 (-67.5, 370)
  midpoint L3 P6
  midpoint L1 P7
  coincident L3 P8
  coincident L1 P9
  perpendicular L1 L6
  symmetric L5 P8 P10
  symmetric L5 P9 P11
  dimension "d51" distance L5 L6 = 60
move "Move19"
move "Move20"
move "Move21"
move "Move22"
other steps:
base_feature "Basiselement"
base_feature "Base Feature"
create_component "Komponente erstellen"
remove_body "Körper entfernen1"
remove_body "Körper entfernen2"
remove_body "Körper entfernen3"
remove_body "Körper entfernen4"
named bodies: "rail"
